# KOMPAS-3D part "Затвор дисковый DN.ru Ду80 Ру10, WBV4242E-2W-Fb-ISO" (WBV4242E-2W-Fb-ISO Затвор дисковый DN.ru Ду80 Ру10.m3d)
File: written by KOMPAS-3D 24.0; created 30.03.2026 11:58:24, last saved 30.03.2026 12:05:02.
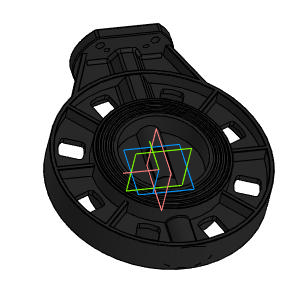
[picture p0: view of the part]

Document properties: Автор: R2D2; Полное имя файла: WBV4242E-2W-Fb-ISO Затвор дисковый DN.ru Ду80 Ру10.cdw

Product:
- Part/product: Затвор дисковый DN.ru Ду80 Ру10  | designation WBV4242E-2W-Fb-ISO
    Масса: 1.37
    Раздел спецификации: Прочие изделия
    Форматы листов документа: A2
    Примечание: D050-81206

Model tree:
1. Операция без истории:2

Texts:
  WBV4242E-2W-Fb-ISO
